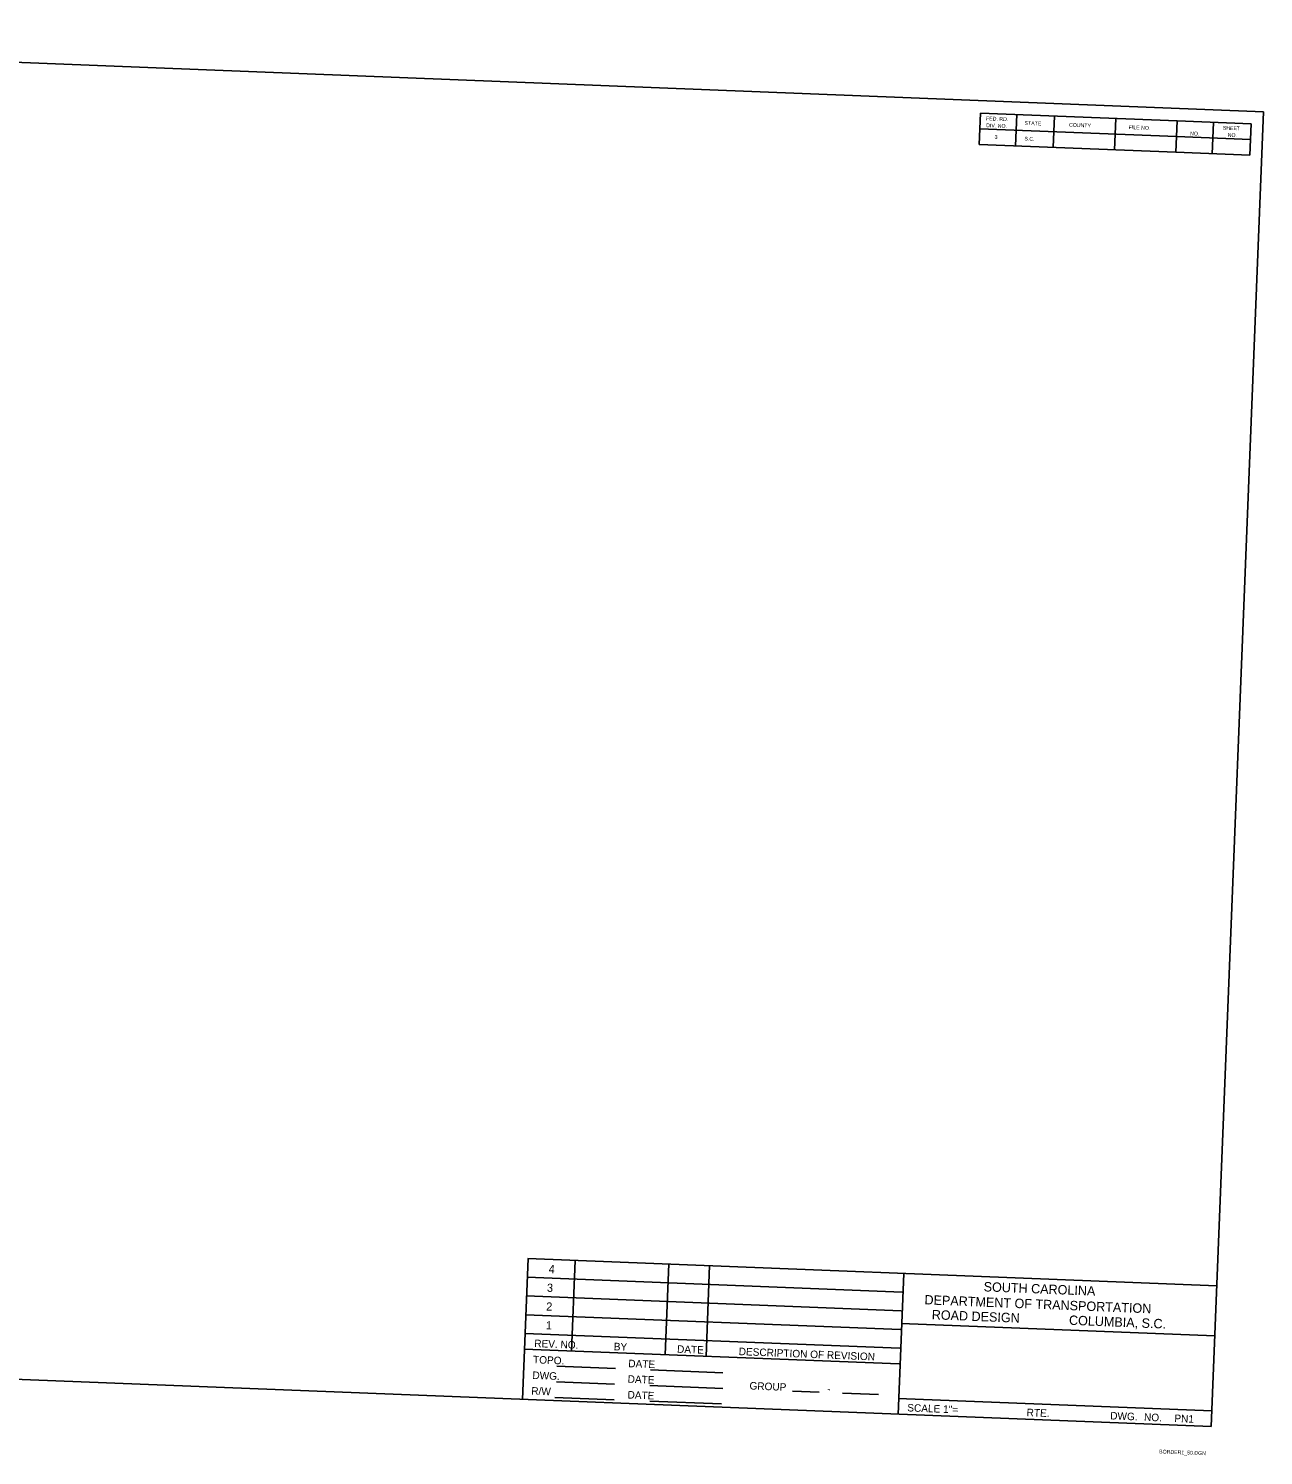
# Model space of a CAD drawing. Extents: x 1965566 to 1970293, y 1116554 to 1118568.
# Drawn here: x 1969307 to 1970293, y 1117298 to 1118437 of the extents above; entities that cross this region are included whole.
import ezdxf

# ---------------------------------------------------------------- set-up
doc = ezdxf.new("R2010")
doc.units = 0
doc.layers.add('Level 1', color=7, linetype='Continuous')

msp = doc.modelspace()

# ---------------------------------------------------------------- linework, layer by layer
at = {"layer": 'Level 1'}
for p, q in [((1970292.6, 1118370.1), (1968618.9, 1118436.6)), ((1970066.8, 1118369.1), (1970065.8, 1118344.1)), ((1970066.8, 1118369.1), (1970223.7, 1118362.8)), ((1970095.8, 1118367.9), (1970094.8, 1118342.9)), ((1970125.8, 1118366.7), (1970124.8, 1118341.8)), ((1970250.9, 1117321), (1970292.6, 1118370.1)), ((1970066.3, 1118356.6), (1970223.2, 1118350.4)), ((1970174.8, 1118364.8), (1970173.8, 1118339.8)), ((1970223.7, 1118362.8), (1970222.7, 1118337.9)), ((1970223.7, 1118362.8), (1970282.7, 1118360.5)), ((1970252.7, 1118361.7), (1970251.7, 1118336.7)), ((1970282.7, 1118360.5), (1970281.7, 1118335.5)), ((1970065.8, 1118344.1), (1970222.7, 1118337.9)), ((1970223.2, 1118350.4), (1970282.2, 1118348)), ((1970222.7, 1118337.9), (1970281.7, 1118335.5)), ((1969701.3, 1117342.6), (1969705.8, 1117455.1)), ((1969705.6, 1117455.2), (1970255.4, 1117433.4)), ((1969740.4, 1117381.1), (1969743.3, 1117453.6)), ((1969815.3, 1117378.1), (1969818.2, 1117450.7)), ((1969847.8, 1117376.8), (1969850.7, 1117449.4)), ((1969705, 1117440.2), (1970004.2, 1117428.3)), ((1970001.1, 1117330.7), (1970005.6, 1117443.2)), ((1969704.4, 1117425.2), (1970003.6, 1117413.3)), ((1969703.8, 1117410.2), (1970003, 1117398.3)), ((1970003.4, 1117403.3), (1970253.8, 1117393.4)), ((1968577.2, 1117387.4), (1970250.9, 1117321)), ((1969703.2, 1117395.2), (1970002.4, 1117383.4)), ((1969702.7, 1117382.7), (1970001.9, 1117370.9)), ((1969728.9, 1117369.2), (1969775.6, 1117367.3)), ((1969803.6, 1117366.2), (1969861.2, 1117363.9)), ((1969728.4, 1117356.7), (1969774.7, 1117354.9)), ((1969803.1, 1117353.7), (1969861.1, 1117351.4)), ((1969727.1, 1117344.2), (1969774.6, 1117342.4)), ((1969916.7, 1117349.2), (1969938.1, 1117348.4)), ((1969956.8, 1117347.6), (1969985.3, 1117346.5)), ((1970001, 1117343.4), (1970251.4, 1117333.4)), ((1969803, 1117341.2), (1969860.2, 1117339))]:
    msp.add_line(p, q, dxfattribs=at)

# ---------------------------------------------------------------- texts
for s, height, p in [('FED. RD.', 3, (1970071.2, 1118363.4)), ('DIV. NO.', 3, (1970071.3, 1118357.9)), ('STATE', 3, (1970101.9, 1118359.7)), ('COUNTY', 3, (1970137.4, 1118358.3)), ('FILE NO.', 3, (1970185, 1118356.4)), ('SHEET', 3, (1970260.1, 1118355.9)), ('3', 3, (1970078, 1118348.6)), ('S.C.', 3, (1970101.8, 1118347.2)), ('NO.', 3, (1970234, 1118351.4)), ('NO.', 3, (1970264, 1118350.2)), ('4', 6.5, (1969722.2, 1117443.5)), ('3', 6.5, (1969720.8, 1117428.6)), ('SOUTH CAROLINA', 7.5, (1970069.2, 1117428.9)), ('DEPARTMENT OF TRANSPORTATION', 7.5, (1970022, 1117418.5)), ('2', 6.5, (1969720.2, 1117413.6)), ('ROAD DESIGN', 7.5, (1970027.8, 1117406.6)), ('1', 6.5, (1969720, 1117398.6)), ('COLUMBIA, S.C.', 7.5, (1970137.3, 1117402.2)), ('REV. NO.', 6, (1969710.7, 1117384.4)), ('BY', 6, (1969774.1, 1117381.9)), ('TOPO.', 6, (1969709.7, 1117371.5)), ('DATE', 6, (1969824.6, 1117379.9)), ('DESCRIPTION OF REVISION', 6, (1969873.8, 1117378)), ('DWG.', 6, (1969709.2, 1117359)), ('DATE', 6, (1969785.7, 1117368.4)), ('DATE', 6, (1969785.2, 1117356)), ('GROUP', 6, (1969882.4, 1117350.6)), ('R/W', 6, (1969708.3, 1117346.5)), ('DATE', 6, (1969785.1, 1117343.4)), ('-', 6, (1969944.3, 1117348.1)), ('SCALE 1"=', 6, (1970008.3, 1117333.1)), ('RTE.', 6, (1970103.5, 1117329.3)), ('DWG.', 6, (1970170.2, 1117326.7)), ('NO.', 6, (1970197.2, 1117325.6)), ('PN1', 6, (1970221.4, 1117324.6)), ('BORDER1_50.DGN', 3, (1970209.3, 1117299.6))]:
    msp.add_text(s, height=height, rotation=357.7266, dxfattribs=at).set_placement(p)

doc.saveas('drawing.dxf')
